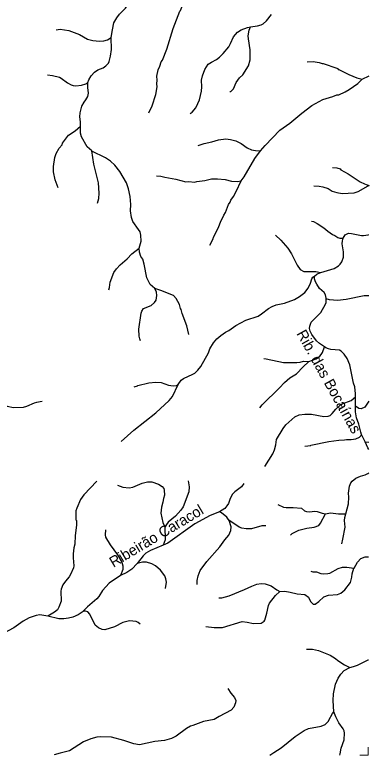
# Model space of a CAD drawing. Extents: x 500 to 555.2, y 9115.7 to 9171.
# Drawn here: x 549.81 to 555.11, y 9115.67 to 9126.76 of the extents above; entities that cross this region are included whole.
import ezdxf
from ezdxf.enums import TextEntityAlignment as Align

# ---------------------------------------------------------------- set-up
doc = ezdxf.new("R2010")
doc.units = 0
doc.header["$LTSCALE"] = 0.064
doc.layers.add('61', color=7, linetype='Continuous')
doc.layers.add('63', color=7, linetype='Continuous', lineweight=13)
doc.layers.add('7', color=7, linetype='Continuous', lineweight=25)

msp = doc.modelspace()

# ---------------------------------------------------------------- linework, layer by layer
at = {"layer": '63'}
msp.add_lwpolyline([(554.9741, 9115.6668), (555.0973, 9115.6668), (555.0973, 9115.7882)], dxfattribs=at)
at = {"layer": '7'}
for p, q in [((555.007, 9125.7974), (555.1127, 9125.849)), ((555.0507, 9120.3628), (554.9994, 9120.4698)), ((555.0507, 9120.3628), (555.1061, 9120.3569))]:
    msp.add_line(p, q, dxfattribs=at)
for points in [[(551.2506, 9126.4218), (551.2671, 9126.5382), (551.2911, 9126.6412), (551.3344, 9126.719), (551.3735, 9126.7699), (551.4649, 9126.8602), (551.5051, 9126.9154), (551.5687, 9127.0263), (551.5917, 9127.1051), (551.5983, 9127.1838), (551.5984, 9127.315), (551.6082, 9127.3937), (551.6268, 9127.4291), (551.6614, 9127.4722), (551.6915, 9127.5316), (551.6984, 9127.5593), (551.7036, 9127.6375), (551.7474, 9127.7416), (551.7582, 9127.7982)], [(551.8111, 9125.2947), (551.8642, 9125.3965), (551.9164, 9125.5666), (551.9378, 9125.6808), (551.933, 9125.7289), (551.9379, 9125.7839), (551.9346, 9125.8447), (551.9528, 9125.9378), (551.9785, 9125.9924), (551.997, 9126.0549), (552.0159, 9126.0836), (552.0837, 9126.2489), (552.1783, 9126.5568), (552.2759, 9126.8178), (552.285, 9126.8276), (552.3364, 9126.9509), (552.3774, 9127.1189), (552.3824, 9127.1608), (552.4004, 9127.2166), (552.4562, 9127.3314), (552.505, 9127.4047), (552.6422, 9127.58)], [(553.3364, 9126.58), (553.4385, 9126.5953), (553.4961, 9126.613), (553.5239, 9126.6278), (553.5748, 9126.6721), (553.6498, 9126.7683)], [(552.4339, 9125.2817), (552.4624, 9125.3025), (552.5164, 9125.3698), (552.549, 9125.4308), (552.5711, 9125.4883), (552.6022, 9125.6196), (552.6069, 9125.6834), (552.6038, 9125.7843), (552.6169, 9125.8486), (552.6516, 9125.9443), (552.7017, 9126.0203), (552.7504, 9126.0545), (552.8279, 9126.0927), (552.8731, 9126.1278), (552.9278, 9126.1842), (553.0098, 9126.2839), (553.0373, 9126.3304), (553.0835, 9126.4335), (553.143, 9126.501), (553.1981, 9126.537), (553.2922, 9126.5734), (553.3364, 9126.58)], [(553.0238, 9125.613), (553.0431, 9125.615), (553.0792, 9125.6535), (553.1201, 9125.7497), (553.1703, 9125.818), (553.2204, 9125.8618), (553.3038, 9125.9957), (553.3295, 9126.0884), (553.3319, 9126.239), (553.304, 9126.4011), (553.3026, 9126.4457), (553.3158, 9126.5294), (553.3364, 9126.58)], [(550.4271, 9126.5343), (550.4879, 9126.5472), (550.6157, 9126.526), (550.7732, 9126.4669), (550.8957, 9126.3944), (550.9725, 9126.3751), (551.0729, 9126.3665), (551.1373, 9126.3703), (551.1958, 9126.3865), (551.2506, 9126.4218)], [(550.9009, 9125.7477), (550.9156, 9125.7893), (550.9484, 9125.8493), (551.0018, 9125.9034), (551.0483, 9125.9367), (551.1288, 9125.969), (551.1717, 9125.9954), (551.207, 9126.0361), (551.2187, 9126.0605), (551.2407, 9126.1406), (551.2537, 9126.2441), (551.2506, 9126.4218)], [(554.1822, 9126.0553), (554.2763, 9126.0618), (554.3617, 9126.0453), (554.407, 9126.0309), (554.423, 9126.0317), (554.6274, 9125.9636), (554.6412, 9125.9548), (554.6466, 9125.9439), (554.6561, 9125.9433), (554.8083, 9125.8666), (554.9298, 9125.8158), (555.007, 9125.7974)], [(550.2983, 9125.8627), (550.3715, 9125.8547), (550.4758, 9125.8267), (550.5019, 9125.8134), (550.5967, 9125.7427), (550.6516, 9125.7108), (550.6819, 9125.7012), (550.7225, 9125.6978), (550.8042, 9125.7063), (550.8687, 9125.7289), (550.9009, 9125.7477)], [(553.4866, 9124.7212), (553.5556, 9124.8021), (553.7771, 9125.0321), (553.9247, 9125.1387), (554.1018, 9125.29), (554.255, 9125.4037), (554.4206, 9125.494), (554.5674, 9125.5365), (554.628, 9125.5614), (554.6588, 9125.5637), (554.7519, 9125.6055), (554.8122, 9125.6407), (554.9423, 9125.7302), (555.007, 9125.7974)], [(550.7919, 9125.0906), (550.7915, 9125.1576), (550.7815, 9125.2345), (550.7847, 9125.2936), (550.8105, 9125.3919), (550.8445, 9125.4536), (550.8712, 9125.4855), (550.9013, 9125.5367), (550.9092, 9125.5887), (550.9013, 9125.6705), (550.9009, 9125.7477)], [(550.4549, 9124.1677), (550.4109, 9124.2897), (550.3862, 9124.4071), (550.3845, 9124.4866), (550.4044, 9124.6255), (550.425, 9124.6828), (550.4714, 9124.7643), (550.5138, 9124.8138), (550.5196, 9124.8375), (550.6116, 9124.9569), (550.7114, 9125.0255), (550.7919, 9125.0906)], [(550.9583, 9124.7211), (550.8913, 9124.7834), (550.8064, 9124.9313), (550.7915, 9124.9886), (550.7919, 9125.0906)], [(552.5505, 9124.8024), (552.6398, 9124.8332), (552.7547, 9124.8563), (552.8544, 9124.8877), (552.9685, 9124.9021), (553.0348, 9124.8954), (553.1154, 9124.8743), (553.1964, 9124.8323), (553.2849, 9124.7705), (553.3523, 9124.738), (553.4121, 9124.7265), (553.4866, 9124.7212)], [(551.0423, 9123.9383), (551.0647, 9124.0097), (551.0717, 9124.0869), (551.0618, 9124.2438), (550.9899, 9124.5226), (550.9583, 9124.7211)], [(551.6689, 9123.265), (551.6967, 9123.3692), (551.6949, 9123.4578), (551.6817, 9123.5078), (551.6605, 9123.5456), (551.5741, 9123.6632), (551.5514, 9123.7266), (551.5394, 9123.8263), (551.5441, 9123.9196), (551.5343, 9124.0371), (551.5097, 9124.1558), (551.4788, 9124.2438), (551.3809, 9124.4147), (551.3051, 9124.5065), (551.239, 9124.5708), (551.1663, 9124.6199), (550.9592, 9124.7203), (550.9583, 9124.7211)], [(553.195, 9124.273), (553.2424, 9124.3329), (553.4013, 9124.6091), (553.4866, 9124.7212)], [(554.5616, 9124.4729), (554.6292, 9124.4672), (554.6759, 9124.4532), (554.6904, 9124.4381), (554.799, 9124.3801), (554.9756, 9124.2571), (555.0412, 9124.2301), (555.0693, 9124.2211), (555.1107, 9124.206)], [(551.9259, 9124.348), (551.9909, 9124.3443), (552.0548, 9124.3267), (552.2152, 9124.2981), (552.3697, 9124.2593), (552.4097, 9124.2624), (552.4984, 9124.2543), (552.5334, 9124.2643), (552.6503, 9124.279), (552.752, 9124.3019), (552.8426, 9124.3051), (552.9581, 9124.292), (553.0523, 9124.2704), (553.1412, 9124.2642), (553.195, 9124.273)], [(552.725, 9123.3075), (552.7752, 9123.4061), (552.7795, 9123.4306), (552.8529, 9123.5621), (552.8953, 9123.679), (552.9266, 9123.7321), (552.9354, 9123.7594), (552.961, 9123.7977), (553.0077, 9123.9173), (553.0319, 9123.9558), (553.0421, 9123.9855), (553.0809, 9124.0398), (553.1214, 9124.1139), (553.195, 9124.273)], [(554.2847, 9124.1989), (554.3632, 9124.1958), (554.4192, 9124.1858), (554.4977, 9124.1567), (554.5607, 9124.1212), (554.6272, 9124.0985), (554.7072, 9124.0855), (554.8879, 9124.0949), (554.9472, 9124.1161), (555.0979, 9124.1989), (555.1107, 9124.206)], [(554.2466, 9123.6692), (554.2773, 9123.6635), (554.3354, 9123.6345), (554.4332, 9123.571), (554.4911, 9123.5219), (554.5656, 9123.4703), (554.5967, 9123.4566), (554.6432, 9123.4248), (554.6725, 9123.4158), (554.7212, 9123.4143)], [(553.7089, 9123.4596), (553.7885, 9123.3861), (553.893, 9123.2669), (553.9487, 9123.1815), (554.0358, 9123.0077), (554.0817, 9122.9469), (554.1337, 9122.9142), (554.3123, 9122.9141), (554.3862, 9122.8995)], [(554.7212, 9123.4143), (554.7542, 9123.4663), (554.805, 9123.4883), (554.8484, 9123.4863), (554.996, 9123.457), (555.0255, 9123.4555), (555.0987, 9123.467), (555.1099, 9123.4688)], [(554.3862, 9122.8995), (554.389, 9122.9007), (554.5864, 9122.9589), (554.6541, 9122.9978), (554.6787, 9123.0225), (554.7043, 9123.0623), (554.7259, 9123.1278), (554.7279, 9123.2077), (554.7099, 9123.3298), (554.7113, 9123.3727), (554.7212, 9123.4143)], [(551.2162, 9122.6413), (551.2263, 9122.6739), (551.2335, 9122.7554), (551.29, 9122.8993), (551.328, 9122.9556), (551.3846, 9123.0171), (551.4891, 9123.1052), (551.561, 9123.1802), (551.6689, 9123.265)], [(551.9018, 9122.6578), (551.8348, 9122.7207), (551.7815, 9122.8225), (551.7435, 9123.0235), (551.7247, 9123.0975), (551.6926, 9123.1383), (551.6725, 9123.203), (551.6689, 9123.265)], [(554.294, 9122.8474), (554.3303, 9122.876), (554.3862, 9122.8995)], [(552.2503, 9121.2215), (552.2976, 9121.2841), (552.332, 9121.3134), (552.4739, 9121.3746), (552.5026, 9121.3924), (552.5475, 9121.4342), (552.5902, 9121.4898), (552.7051, 9121.6948), (552.7288, 9121.7583), (552.7817, 9121.845), (552.8339, 9121.9058), (552.892, 9121.9574), (552.9634, 9122.0062), (553.0126, 9122.0324), (553.1175, 9122.1063), (553.2674, 9122.1854), (553.4493, 9122.2446), (553.5014, 9122.2784), (553.6038, 9122.3593), (553.6615, 9122.3915), (553.721, 9122.4151), (553.8424, 9122.4429), (553.992, 9122.4978), (554.0695, 9122.5398), (554.1478, 9122.6014), (554.1978, 9122.6638), (554.2323, 9122.738), (554.2537, 9122.8063), (554.2697, 9122.8296), (554.294, 9122.8474)], [(554.4689, 9122.5067), (554.4692, 9122.5171), (554.4605, 9122.567), (554.4364, 9122.6004), (554.3704, 9122.6616), (554.3275, 9122.723), (554.3097, 9122.7584), (554.2953, 9122.8043), (554.294, 9122.8474)], [(551.6895, 9121.8776), (551.6763, 9121.9055), (551.6686, 9121.9465), (551.6639, 9122.0497), (551.6984, 9122.2918), (551.7073, 9122.3195), (551.7347, 9122.3596), (551.8492, 9122.4073), (551.8979, 9122.4495), (551.9212, 9122.4845), (551.9324, 9122.5572), (551.928, 9122.6067), (551.9018, 9122.6578)], [(552.4126, 9121.9715), (552.3809, 9122.1011), (552.3117, 9122.2866), (552.2984, 9122.3431), (552.2855, 9122.3619), (552.2722, 9122.4203), (552.2237, 9122.5099), (552.1829, 9122.5559), (551.9923, 9122.6325), (551.9018, 9122.6578)], [(554.443, 9121.7855), (554.3699, 9121.8353), (554.3237, 9121.8781), (554.2523, 9121.971), (554.2275, 9122.0208), (554.2195, 9122.0595), (554.2225, 9122.0968), (554.2422, 9122.1574), (554.3874, 9122.3017), (554.4602, 9122.4232), (554.4672, 9122.4486), (554.4689, 9122.5067)], [(555.1087, 9122.5491), (555.0891, 9122.5498), (555.0395, 9122.5515), (554.7668, 9122.4961), (554.6404, 9122.4795), (554.5178, 9122.4905), (554.4689, 9122.5067)], [(554.2112, 9121.5645), (554.3168, 9121.6072), (554.3725, 9121.6466), (554.3936, 9121.6697), (554.4116, 9121.7011), (554.443, 9121.7855)], [(554.9087, 9121.037), (554.9099, 9121.0836), (554.8957, 9121.1878), (554.8771, 9121.2434), (554.8247, 9121.515), (554.7827, 9121.612), (554.7394, 9121.6757), (554.6944, 9121.7213), (554.6673, 9121.7349), (554.5372, 9121.7457), (554.5014, 9121.7541), (554.4617, 9121.7727), (554.443, 9121.7855)], [(553.5347, 9121.6098), (553.5696, 9121.6081), (553.8274, 9121.5512), (554.0281, 9121.5512), (554.0774, 9121.5561), (554.1293, 9121.5706), (554.2112, 9121.5645)], [(553.4774, 9120.87), (553.5103, 9120.9173), (553.772, 9121.1708), (553.843, 9121.2534), (553.9231, 9121.3217), (554.0268, 9121.3832), (554.1231, 9121.4859), (554.2062, 9121.5625), (554.2112, 9121.5645)], [(551.5955, 9121.1857), (551.6447, 9121.2026), (551.6496, 9121.2086), (551.8126, 9121.2474), (551.9181, 9121.2573), (551.9985, 9121.2523), (552.1063, 9121.2138), (552.1797, 9121.2002), (552.2271, 9121.2064), (552.2503, 9121.2215)], [(551.3988, 9120.3658), (551.5876, 9120.5382), (551.9186, 9120.7986), (552.1162, 9120.9815), (552.1672, 9121.0395), (552.2503, 9121.2215)], [(550.2166, 9120.9656), (550.1291, 9120.9527), (550.0941, 9120.9425), (549.9822, 9120.8927), (549.9301, 9120.8786), (549.7825, 9120.8737), (549.6975, 9120.8894), (549.6304, 9120.9292), (549.5495, 9121.0048), (549.5133, 9121.053)], [(553.5526, 9119.9914), (553.668, 9120.1825), (553.6961, 9120.2421), (553.7158, 9120.3181), (553.7269, 9120.3976), (553.8261, 9120.5634), (553.8664, 9120.6189), (553.9986, 9120.7376), (554.0655, 9120.7671), (554.1483, 9120.7784), (554.25, 9120.7753), (554.4337, 9120.7425), (554.5005, 9120.7461), (554.5266, 9120.7593), (554.5597, 9120.7861), (554.6119, 9120.8528), (554.6831, 9120.9174), (554.7107, 9120.9329), (554.8449, 9120.9835), (554.9087, 9121.037)], [(555.1068, 9120.972), (555.0982, 9120.9591), (555.0481, 9120.8843), (554.9915, 9120.8589), (554.9596, 9120.8617), (554.9096, 9120.8971), (554.9087, 9121.037)], [(554.9994, 9120.4698), (554.986, 9120.5076), (554.9554, 9120.6256), (554.9216, 9120.7243), (554.9101, 9120.8123), (554.9096, 9120.8971)], [(554.1512, 9120.295), (554.238, 9120.3078), (554.2413, 9120.3125), (554.5104, 9120.3652), (554.6574, 9120.3864), (554.7439, 9120.3912), (554.7707, 9120.3976), (554.8444, 9120.3951), (554.9104, 9120.4055), (554.9702, 9120.4322), (554.9899, 9120.4518), (554.9994, 9120.4698)], [(555.106, 9120.2473), (555.0945, 9120.2713), (555.0507, 9120.3628)], [(554.7624, 9119.2848), (554.8034, 9119.4318), (554.8084, 9119.5309), (554.8019, 9119.5908), (554.8171, 9119.6988), (554.8399, 9119.7477), (554.8592, 9119.7746), (554.9127, 9119.8168), (554.9824, 9119.8464), (555.053, 9119.8677), (555.0921, 9119.8895), (555.1056, 9119.897)], [(551.0336, 9119.7707), (550.8375, 9119.5698), (550.788, 9119.499), (550.7346, 9119.3704), (550.7225, 9119.3269), (550.7224, 9119.1951), (550.7289, 9119.184), (550.7304, 9119.113), (550.7093, 9118.9594), (550.7058, 9118.8308), (550.6912, 9118.7724), (550.678, 9118.6832), (550.678, 9118.6255), (550.6894, 9118.506), (550.683, 9118.474), (550.6419, 9118.3755), (550.6188, 9118.3402), (550.5645, 9118.2765), (550.5264, 9118.2187), (550.5013, 9118.1562), (550.4961, 9118.1261), (550.4993, 9117.9759), (550.4677, 9117.8829), (550.4445, 9117.8421), (550.4025, 9117.808), (550.3, 9117.7512)], [(551.3418, 9119.711), (551.4235, 9119.6829), (551.5179, 9119.6746), (551.5733, 9119.6838), (551.7115, 9119.7434), (551.794, 9119.7616), (551.8561, 9119.7647), (551.9575, 9119.7302), (552.0116, 9119.6909), (552.0371, 9119.6637), (552.0445, 9119.6393), (552.0476, 9119.5619), (552.0314, 9119.5138), (552.0244, 9119.4599), (552.0052, 9119.3833), (551.9937, 9119.2931), (552.0219, 9119.1552), (552.0511, 9119.0883)], [(552.4018, 9119.7771), (552.4167, 9119.6883), (552.4132, 9119.615), (552.3281, 9119.3892), (552.2913, 9119.3389), (552.2121, 9119.2502), (552.1023, 9119.1598), (552.0511, 9119.0883)], [(553.2373, 9119.7382), (553.2029, 9119.6882), (553.102, 9119.6117), (553.0683, 9119.578), (553.0307, 9119.5131), (553.0055, 9119.4385), (552.983, 9119.4011), (552.9494, 9119.361), (552.8705, 9119.3138)], [(553.7468, 9119.4213), (553.8302, 9119.3846), (553.8701, 9119.3777), (553.9762, 9119.3775), (554.0975, 9119.3668), (554.1463, 9119.3301), (554.1726, 9119.3186), (554.2173, 9119.3145), (554.2998, 9119.3234), (554.3363, 9119.319), (554.4065, 9119.2946), (554.4576, 9119.2857)], [(552.8705, 9119.3138), (552.7336, 9119.2605), (552.504, 9119.1357), (552.0953, 9118.8446), (552.0259, 9118.8143)], [(553.0141, 9119.1821), (553.0249, 9119.1664), (552.9788, 9119.2335), (552.9024, 9119.2984), (552.8705, 9119.3138)], [(553.9365, 9118.9617), (553.9599, 9118.9867), (554.0609, 9119.0367), (554.1779, 9119.0675), (554.2899, 9119.0842), (554.3569, 9119.1104), (554.3841, 9119.141), (554.4576, 9119.2857)], [(554.4576, 9119.2857), (554.5327, 9119.3004), (554.6515, 9119.2808), (554.7624, 9119.2848)], [(554.7014, 9118.8354), (554.7195, 9118.9031), (554.7509, 9119.084), (554.7427, 9119.1813), (554.7461, 9119.2263), (554.7624, 9119.2848)], [(552.5362, 9118.2231), (552.5346, 9118.2848), (552.5513, 9118.3525), (552.5839, 9118.4339), (552.6796, 9118.5695), (552.8781, 9118.7876), (552.9491, 9118.8912), (553.0101, 9118.9655), (553.0431, 9119.0359), (553.0466, 9119.09), (553.0141, 9119.1821)], [(553.5642, 9119.1019), (553.5074, 9119.1033), (553.3528, 9119.0597), (553.2725, 9119.0563), (553.2049, 9119.0682), (553.1635, 9119.0813), (553.0707, 9119.1498), (553.0141, 9119.1821)], [(551.1651, 9119.0435), (551.1586, 9118.9695), (551.1661, 9118.9348), (551.2345, 9118.8164), (551.3417, 9118.6693), (551.4092, 9118.5589), (551.426, 9118.5061), (551.426, 9118.4477), (551.3881, 9118.3597)], [(552.0511, 9119.0883), (552.0591, 9118.8933), (552.0259, 9118.8143)], [(552.0259, 9118.8143), (551.8376, 9118.7321), (551.7706, 9118.6952), (551.7268, 9118.6527), (551.64, 9118.5367)], [(554.8849, 9118.4676), (554.886, 9118.471), (554.9397, 9118.559), (554.9886, 9118.6123), (555.0537, 9118.6376), (555.0987, 9118.638), (555.104, 9118.638)], [(551.64, 9118.5367), (551.5578, 9118.4557), (551.4843, 9118.4047), (551.3881, 9118.3597)], [(552.0634, 9118.1629), (552.0756, 9118.2568), (552.0699, 9118.3085), (552.0509, 9118.3558), (551.9886, 9118.4378), (551.9148, 9118.5017), (551.8563, 9118.5343), (551.777, 9118.5575), (551.7186, 9118.5575), (551.64, 9118.5367)], [(553.7751, 9118.1188), (553.8511, 9118.1244), (553.9298, 9118.1113), (554.0335, 9118.0836), (554.1479, 9118.0722), (554.2026, 9118.0324), (554.2323, 9117.9675), (554.2726, 9117.9293), (554.3042, 9117.9277), (554.3605, 9117.9704), (554.4323, 9118.0381), (554.5051, 9118.0651), (554.6391, 9118.0758), (554.6869, 9118.0966), (554.7492, 9118.1459), (554.8314, 9118.2548), (554.8526, 9118.3328), (554.8592, 9118.3853), (554.8849, 9118.4676)], [(554.2395, 9118.422), (554.2698, 9118.4146), (554.3223, 9118.4116), (554.3879, 9118.3904), (554.4272, 9118.3853), (554.4929, 9118.387), (554.5221, 9118.3963), (554.649, 9118.4644), (554.7126, 9118.4819), (554.7803, 9118.482), (554.8849, 9118.4676)], [(551.3881, 9118.3597), (551.2194, 9118.2458), (551.121, 9118.1359), (551.0627, 9118.0421), (551.0353, 9118.0094), (550.8934, 9117.8919), (550.8291, 9117.823)], [(552.8591, 9118.0232), (552.9084, 9118.0262), (553.0177, 9118.0541), (553.2475, 9118.15), (553.3569, 9118.2015), (553.4318, 9118.2292), (553.4954, 9118.2375), (553.5577, 9118.2322), (553.6431, 9118.205), (553.7317, 9118.1429), (553.7751, 9118.1188)], [(552.6691, 9117.593), (552.7902, 9117.5783), (552.9169, 9117.5813), (553.2108, 9117.6699), (553.2856, 9117.6619), (553.3818, 9117.639), (553.494, 9117.6445), (553.5383, 9117.6753), (553.5486, 9117.6921), (553.5799, 9117.7922), (553.6056, 9117.9082), (553.6205, 9117.9433), (553.7099, 9118.0593), (553.7751, 9118.1188)], [(550.8291, 9117.823), (550.8276, 9117.8214), (550.7535, 9117.7686), (550.6771, 9117.7336), (550.6109, 9117.7175), (550.541, 9117.7095), (550.4653, 9117.7116), (550.3, 9117.7512)], [(551.6828, 9117.6281), (551.6524, 9117.6554), (551.6237, 9117.6683), (551.5244, 9117.6799), (551.4255, 9117.6551), (551.3014, 9117.5898), (551.1531, 9117.5455), (551.1157, 9117.5485), (551.0598, 9117.573), (551.0115, 9117.6155), (550.9273, 9117.7784), (550.9009, 9117.8154), (550.8673, 9117.8256), (550.8291, 9117.823)], [(550.3, 9117.7512), (550.2984, 9117.7516), (550.1801, 9117.7684), (550.1286, 9117.7618), (550.0193, 9117.7229), (549.9307, 9117.6754), (549.7916, 9117.5768), (549.6133, 9117.4806), (549.5456, 9117.436), (549.3659, 9117.2961), (549.1262, 9117.0479), (549.0465, 9116.9931), (548.9466, 9116.9546), (548.8031, 9116.9419), (548.6829, 9116.9485), (548.4617, 9116.9928)], [(554.175, 9117.2553), (554.2631, 9117.2536), (554.3523, 9117.2371), (554.5294, 9117.1632), (554.6104, 9117.1131), (554.6432, 9117.0858), (554.7454, 9117.021), (554.8254, 9116.9813)], [(554.8254, 9116.9813), (554.8763, 9116.993), (554.938, 9117.0136), (555.0987, 9117.0944), (555.1022, 9117.0961)], [(554.5846, 9116.3184), (554.5738, 9116.4876), (554.5787, 9116.5849), (554.6077, 9116.7305), (554.6485, 9116.8191), (554.6866, 9116.8789), (554.7395, 9116.9351), (554.8254, 9116.9813)], [(552.9983, 9116.6668), (553.0397, 9116.598), (553.0984, 9116.5294), (553.1141, 9116.488), (553.1123, 9116.4503), (553.0869, 9116.3848), (553.0481, 9116.3433), (552.8644, 9116.2455), (552.7935, 9116.1988), (552.6339, 9116.1711), (552.4702, 9116.1104), (552.435, 9116.1029), (552.3754, 9116.0684), (552.221, 9115.9524), (552.1508, 9115.9167), (552.0493, 9115.8872), (551.9011, 9115.8722), (551.6739, 9115.8232), (551.5875, 9115.8361), (551.4405, 9115.8883), (551.2529, 9115.9345), (551.0954, 9115.9396), (551.0357, 9115.9363), (550.9465, 9115.9115), (550.8353, 9115.8641), (550.6273, 9115.7324), (550.4862, 9115.6953), (550.3939, 9115.671)], [(553.6274, 9115.6673), (553.6839, 9115.7045), (553.7958, 9115.7781), (554.0057, 9115.9454), (554.1386, 9116.0377), (554.2054, 9116.0645), (554.3935, 9116.1016), (554.454, 9116.1267), (554.5056, 9116.1783), (554.5069, 9116.1894), (554.5623, 9116.2923), (554.5846, 9116.3184)], [(554.6742, 9115.6661), (554.6776, 9115.6853), (554.6934, 9115.7738), (554.7361, 9115.8987), (554.7426, 9115.997), (554.7377, 9116.0297), (554.722, 9116.0614), (554.6598, 9116.1526), (554.6121, 9116.2385), (554.5846, 9116.3184)]]:
    msp.add_lwpolyline(points, dxfattribs=at)

# ---------------------------------------------------------------- texts
at = {"layer": '61'}
for s, rotation, p in [('Rib. das Bocaínas', 299.055, (554.4415, 9121.2271)), ('Ribeirão Caracol', 30.964, (551.9664, 9118.8841))]:
    msp.add_text(s, height=0.16, rotation=rotation, dxfattribs=at).set_placement(p, align=Align.CENTER)

doc.saveas('drawing.dxf')
